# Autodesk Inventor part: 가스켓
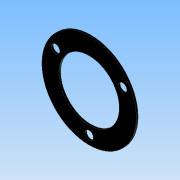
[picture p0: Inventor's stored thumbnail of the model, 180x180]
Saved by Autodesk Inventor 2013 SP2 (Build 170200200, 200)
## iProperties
Created: 2025-10
Part Number: 가스켓
Material: Generic
Document SubType Name: Modeling
Designer: a
Density: 1 g/cm^3
Author: a
변환 표준: STEP AP214IS
전처리기: Build: 200, Release: 2013 SP2 Update 6 - Date: Thu 07/17/2014
전송 단위: 밀리미터
불확실성: 0.01
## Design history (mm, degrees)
node "가스켓1"
node "솔리드1"
node "기준1"
